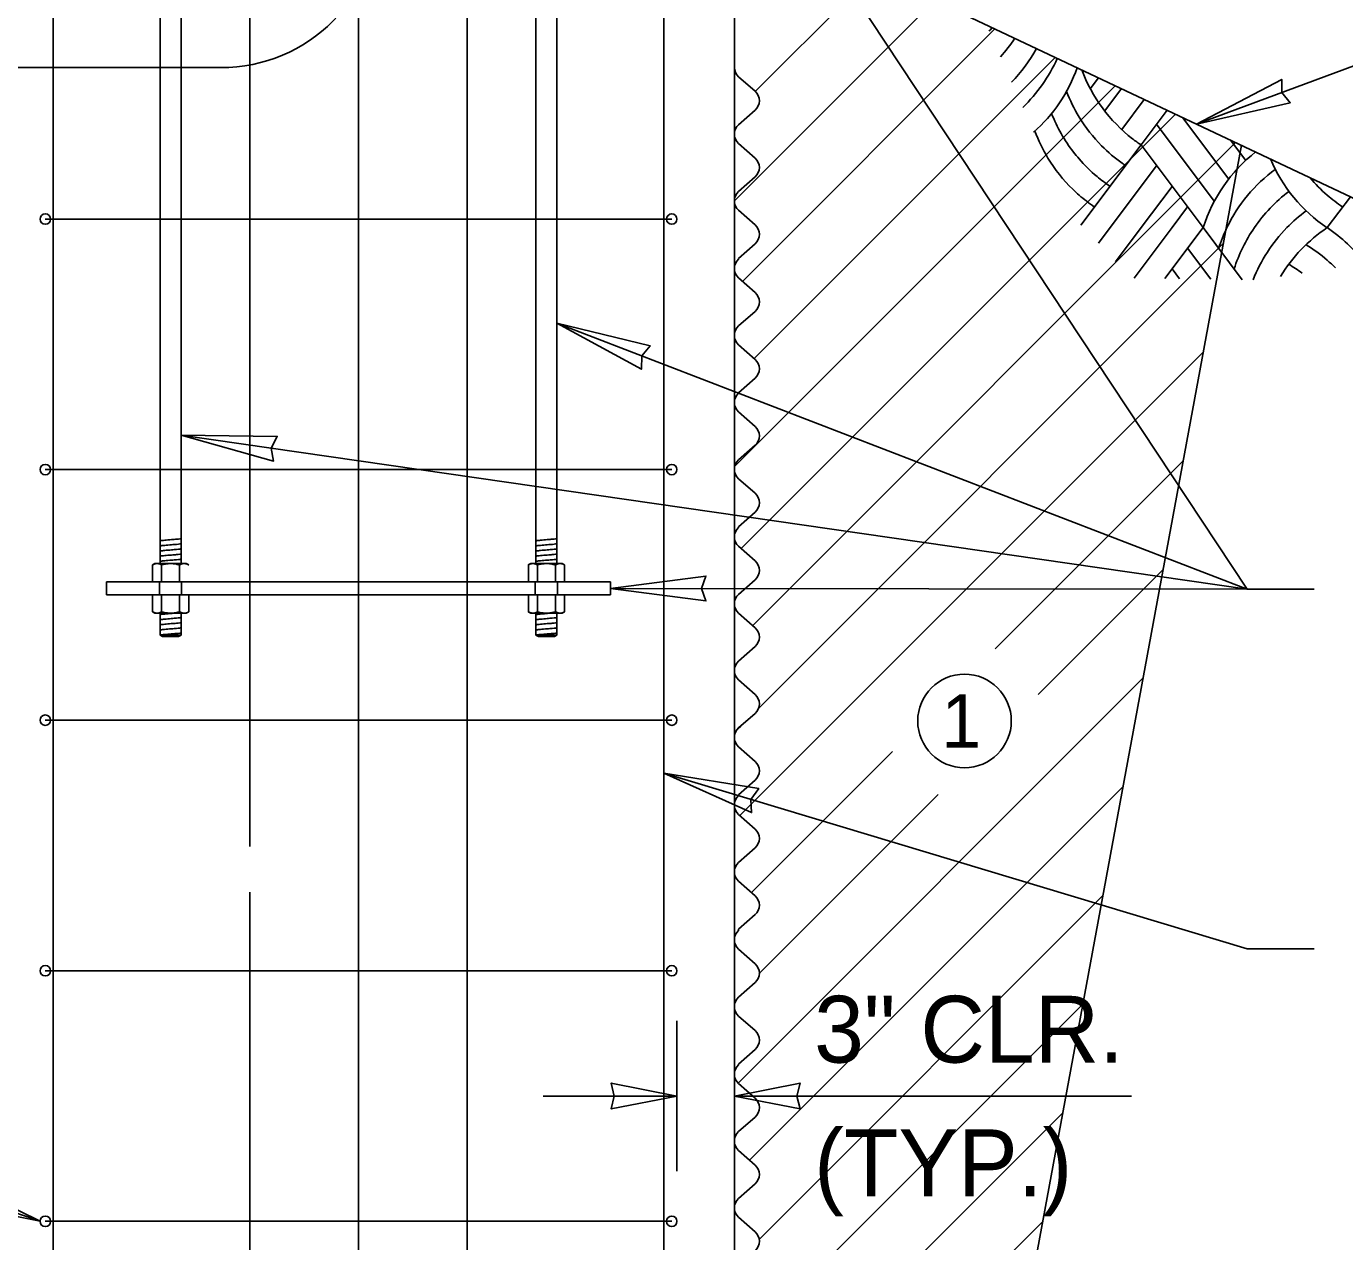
# Model space of a CAD drawing. Extents: x 99862 to 103151, y 100000 to 102076.
# Drawn here: x 101685.3 to 102001, y 101394.1 to 101685.1 of the extents above; entities that cross this region are included whole.
import ezdxf

# ---------------------------------------------------------------- set-up
doc = ezdxf.new("R2010")
doc.units = 0
for name, color, linetype in [('Level 13', 7, 'Continuous'), ('Level 15', 7, 'Continuous'), ('Level 17', 7, 'Continuous'), ('Level 2', 7, 'Continuous'), ('Level 20', 7, 'Continuous'), ('Level 23', 7, 'Continuous'), ('Level 59', 7, 'Continuous'), ('Level 6', 7, 'Continuous'), ('Level 9', 7, 'Continuous')]:
    doc.layers.add(name, color=color, linetype=linetype)

msp = doc.modelspace()

# ---------------------------------------------------------------- linework, layer by layer
at = {"layer": 'Level 13'}
for p, q in [((101691.69, 101338.99), (101691.69, 101798.99)), ((101738.77, 101488.74), (101738.77, 101798.99)), ((101790.85, 101338.99), (101790.85, 101798.99)), ((101837.94, 101338.99), (101837.94, 101798.99)), ((101859.82, 101669.54), (101888.41, 101698.12)), ((101854.82, 101643.32), (101902.81, 101691.32)), ((101856.77, 101624.06), (101917.22, 101684.51)), ((101859.54, 101605.61), (101931.63, 101677.71)), ((101854.95, 101579.82), (101946.04, 101670.91)), ((101856.43, 101560.08), (101960.45, 101664.1)), ((101859.2, 101541.64), (101974.86, 101657.3)), ((101976.23, 101656.65), (101914.81, 101323.99)), ((101839.81, 101638.99), (101689.81, 101638.99)), ((101860.57, 101521.79), (101971.88, 101633.11)), ((101856.14, 101496.15), (101967.08, 101607.09)), ((101839.81, 101578.99), (101689.81, 101578.99)), ((101917.26, 101536.06), (101962.27, 101581.07)), ((101927.56, 101525.15), (101957.47, 101555.06)), ((101855.73, 101432.1), (101952.67, 101529.04)), ((101839.81, 101518.99), (101689.81, 101518.99)), ((101855.74, 101516.96), (101856.36, 101517.58)), ((101858.91, 101477.71), (101892.69, 101511.49)), ((101858.47, 101413.63), (101947.87, 101503.02)), ((101860.66, 101458.25), (101903.6, 101501.18)), ((101738.77, 101338.99), (101738.77, 101477.79)), ((101860.73, 101394.67), (101943.06, 101477.01)), ((101839.81, 101458.99), (101689.81, 101458.99)), ((101855.48, 101368.22), (101938.26, 101450.99)), ((101858.18, 101349.69), (101933.46, 101424.98)), ((101839.81, 101398.99), (101689.81, 101398.99)), ((101860.47, 101330.77), (101928.65, 101398.96))]:
    msp.add_line(p, q, dxfattribs=at)
for centre in [(101689.81, 101638.99), (101839.81, 101638.99), (101689.81, 101578.99), (101839.81, 101578.99), (101689.81, 101518.99), (101839.81, 101518.99), (101689.81, 101458.99), (101839.81, 101458.99), (101689.81, 101398.99), (101839.81, 101398.99)]:
    msp.add_circle(centre, 1.25, dxfattribs=at)
at = {"layer": 'Level 15'}
for p, q in [((101764.81, 101307.99), (101764.81, 102030.59)), ((101977.65, 101550.4), (101825.18, 101780.68)), ((101965.5, 101661.72), (102090.32, 101707.91)), ((101977.65, 101550.4), (101812.31, 101614.02)), ((101977.65, 101550.4), (101722.31, 101587.24)), ((101825.18, 101550.55), (101977.65, 101550.4)), ((101993.65, 101550.4), (101977.65, 101550.4)), ((101837.94, 101506.32), (101977.65, 101464.2)), ((101993.65, 101464.2), (101977.65, 101464.2)), ((101841.06, 101446.99), (101841.06, 101410.99)), ((101688.56, 101398.99), (101560.03, 101442.65)), ((101841.06, 101428.99), (101809.06, 101428.99)), ((101949.93, 101428.99), (101854.81, 101428.99))]:
    msp.add_line(p, q, dxfattribs=at)
for points in [[(101965.5, 101661.72), (101987.95, 101666.84), (101985.92, 101669.27), (101985.88, 101672.44)], [(101812.31, 101614.02), (101832.54, 101603.03), (101832.63, 101606.2), (101834.69, 101608.6)], [(101722.31, 101587.24), (101744.48, 101581.03), (101743.86, 101584.13), (101745.33, 101586.94)], [(101825.18, 101550.55), (101848.01, 101547.54), (101846.96, 101550.53), (101848.02, 101553.51)], [(101837.94, 101506.32), (101858.93, 101496.87), (101858.78, 101500.03), (101860.66, 101502.59)], [(101841.06, 101428.99), (101825.34, 101425.9), (101826.07, 101428.99), (101825.34, 101432.07)], [(101854.81, 101428.99), (101870.54, 101425.9), (101869.81, 101428.99), (101870.54, 101432.07)], [(101688.56, 101398.99), (101665.99, 101403.5), (101667.95, 101405.99), (101667.91, 101409.16)]]:
    msp.add_lwpolyline(points, close=True, dxfattribs=at)
at = {"layer": 'Level 17'}
for p, q in [((101859.8, 101669.58), (101855.83, 101673.08)), ((101855.83, 101661.58), (101859.8, 101665.08)), ((101859.8, 101653.58), (101855.83, 101657.08)), ((101855.83, 101645.58), (101859.8, 101649.08)), ((101859.8, 101637.58), (101855.83, 101641.08)), ((101855.83, 101629.58), (101859.8, 101633.08)), ((101855.83, 101629.38), (101855.83, 101629.58)), ((101859.8, 101621.38), (101855.83, 101624.88)), ((101855.83, 101613.38), (101859.8, 101616.88)), ((101859.8, 101605.38), (101855.83, 101608.88)), ((101855.83, 101597.38), (101859.8, 101600.88)), ((101855.83, 101597.31), (101855.83, 101597.38)), ((101859.8, 101589.31), (101855.83, 101592.81)), ((101855.83, 101581.31), (101859.8, 101584.81)), ((101859.8, 101573.31), (101855.83, 101576.81)), ((101855.83, 101565.31), (101859.8, 101568.81)), ((101855.83, 101565.12), (101855.83, 101565.31)), ((101859.8, 101557.12), (101855.83, 101560.62)), ((101855.83, 101549.12), (101859.8, 101552.62)), ((101859.8, 101541.12), (101855.83, 101544.62)), ((101855.83, 101533.12), (101859.8, 101536.62)), ((101859.8, 101525.12), (101855.83, 101528.62)), ((101855.83, 101517.12), (101859.8, 101520.62)), ((101859.8, 101509.12), (101855.83, 101512.62)), ((101855.83, 101501.12), (101859.8, 101504.62)), ((101855.83, 101500.92), (101855.83, 101501.12)), ((101859.8, 101492.92), (101855.83, 101496.42)), ((101855.83, 101484.92), (101859.8, 101488.42)), ((101859.8, 101476.92), (101855.83, 101480.42)), ((101855.83, 101468.92), (101859.8, 101472.42)), ((101855.83, 101468.65), (101855.83, 101468.92)), ((101859.8, 101460.65), (101855.83, 101464.15)), ((101855.83, 101452.65), (101859.8, 101456.15)), ((101859.8, 101444.65), (101855.83, 101448.15)), ((101855.83, 101436.65), (101859.8, 101440.15)), ((101855.83, 101436.46), (101855.83, 101436.65)), ((101859.8, 101428.46), (101855.83, 101431.96)), ((101855.83, 101420.46), (101859.8, 101423.96)), ((101859.8, 101412.46), (101855.83, 101415.96)), ((101855.83, 101404.46), (101859.8, 101407.96)), ((101859.8, 101396.46), (101855.83, 101399.96))]:
    msp.add_line(p, q, dxfattribs=at)
for centre, start, end in [((101857.81, 101675.33), 181.5884, 228.5904), ((101857.81, 101667.33), 311.4096, 48.5904), ((101857.81, 101659.33), 131.4096, 228.5904), ((101857.81, 101651.33), 311.4096, 48.5904), ((101857.81, 101643.33), 131.4096, 228.5904), ((101857.81, 101635.33), 311.4096, 48.5904), ((101857.81, 101627.13), 131.4096, 228.5904), ((101857.81, 101619.13), 311.4096, 48.5904), ((101857.81, 101611.13), 131.4096, 228.5904), ((101857.81, 101603.13), 311.4096, 48.5904), ((101857.81, 101595.06), 131.4096, 228.5904), ((101857.81, 101587.06), 311.4096, 48.5904), ((101857.81, 101579.06), 131.4096, 228.5904), ((101857.81, 101571.06), 311.4096, 48.5904), ((101857.81, 101562.87), 131.4096, 228.5904), ((101857.81, 101554.87), 311.4096, 48.5904), ((101857.81, 101546.87), 131.4096, 228.5904), ((101857.81, 101538.87), 311.4096, 48.5904), ((101857.81, 101530.87), 131.4096, 228.5904), ((101857.81, 101522.87), 311.4096, 48.5904), ((101857.81, 101514.87), 131.4096, 228.5904), ((101857.81, 101506.87), 311.4096, 48.5904), ((101857.81, 101498.67), 131.4096, 228.5904), ((101857.81, 101490.67), 311.4096, 48.5904), ((101857.81, 101482.67), 131.4096, 228.5904), ((101857.81, 101474.67), 311.4096, 48.5904), ((101857.81, 101466.4), 131.4096, 228.5904), ((101857.81, 101458.4), 311.4096, 48.5904), ((101857.81, 101450.4), 131.4096, 228.5904), ((101857.81, 101442.4), 311.4096, 48.5904), ((101857.81, 101434.21), 131.4096, 228.5904), ((101857.81, 101426.21), 311.4096, 48.5904), ((101857.81, 101418.21), 131.4096, 228.5904), ((101857.81, 101410.21), 311.4096, 48.5904), ((101857.81, 101402.21), 131.4096, 228.5904), ((101857.81, 101394.21), 311.4096, 48.5904)]:
    msp.add_arc(centre, 3, start, end, dxfattribs=at)
at = {"layer": 'Level 2'}
msp.add_line((101854.81, 101323.99), (101854.81, 101803.99), dxfattribs=at)
at = {"layer": 'Level 20'}
msp.add_circle((101909.93, 101518.81), 11.2, dxfattribs=at)
at = {"layer": 'Level 23'}
for p, q in [((101717.31, 101776.3), (101717.31, 101556.49)), ((101722.31, 101776.3), (101722.31, 101556.49)), ((101807.31, 101776.3), (101807.31, 101556.49)), ((101812.31, 101776.3), (101812.31, 101556.49)), ((101825.18, 101552.11), (101704.43, 101552.11)), ((101704.43, 101552.11), (101704.43, 101548.99)), ((101717.15, 101552.11), (101717.15, 101548.99)), ((101722.46, 101552.11), (101722.46, 101548.99)), ((101807.15, 101552.11), (101807.15, 101548.99)), ((101812.46, 101552.11), (101812.46, 101548.99)), ((101825.18, 101548.99), (101825.18, 101552.11)), ((101704.43, 101548.99), (101825.18, 101548.99)), ((101717.31, 101544.61), (101717.31, 101539.33)), ((101722.31, 101544.61), (101722.31, 101539.33)), ((101807.31, 101544.61), (101807.31, 101539.33)), ((101812.31, 101544.61), (101812.31, 101539.33)), ((101717.91, 101538.99), (101717.31, 101539.33)), ((101722.31, 101539.33), (101717.31, 101539.33)), ((101717.91, 101538.99), (101721.71, 101538.99)), ((101721.71, 101538.99), (101722.31, 101539.33)), ((101812.31, 101539.33), (101807.31, 101539.33)), ((101807.91, 101538.99), (101807.31, 101539.33)), ((101807.91, 101538.99), (101811.71, 101538.99)), ((101811.71, 101538.99), (101812.31, 101539.33))]:
    msp.add_line(p, q, dxfattribs=at)
for points in [[(101717.33, 101561.92), (101717.34, 101561.93), (101717.34, 101561.93), (101717.48, 101562), (101718.22, 101562.06), (101720.13, 101562.24), (101721.28, 101562.32), (101722.12, 101562.42), (101722.27, 101562.45), (101722.31, 101562.49)], [(101717.33, 101560.69), (101717.34, 101560.7), (101717.34, 101560.7), (101717.48, 101560.77), (101718.22, 101560.83), (101720.13, 101561.02), (101721.28, 101561.09), (101722.12, 101561.19), (101722.27, 101561.22), (101722.31, 101561.26)], [(101717.33, 101559.47), (101717.34, 101559.47), (101717.34, 101559.47), (101717.48, 101559.54), (101718.22, 101559.61), (101720.14, 101559.79), (101721.28, 101559.86), (101722.12, 101559.96), (101722.27, 101560), (101722.31, 101560.03)], [(101807.33, 101561.92), (101807.34, 101561.93), (101807.34, 101561.93), (101807.48, 101562), (101808.22, 101562.06), (101810.13, 101562.24), (101811.28, 101562.32), (101812.12, 101562.42), (101812.27, 101562.45), (101812.31, 101562.49)], [(101807.33, 101560.69), (101807.34, 101560.7), (101807.34, 101560.7), (101807.48, 101560.77), (101808.22, 101560.83), (101810.13, 101561.02), (101811.28, 101561.09), (101812.12, 101561.19), (101812.27, 101561.22), (101812.31, 101561.26)], [(101807.33, 101559.47), (101807.34, 101559.47), (101807.34, 101559.47), (101807.48, 101559.54), (101808.22, 101559.61), (101810.14, 101559.79), (101811.28, 101559.86), (101812.12, 101559.96), (101812.27, 101560), (101812.31, 101560.03)], [(101717.32, 101558.24), (101717.32, 101558.24), (101717.32, 101558.24), (101717.47, 101558.31), (101718.2, 101558.38), (101720.12, 101558.56), (101721.26, 101558.63), (101722.1, 101558.73), (101722.26, 101558.77), (101722.29, 101558.8)], [(101717.33, 101557.01), (101717.34, 101557.01), (101717.34, 101557.01), (101717.48, 101557.08), (101718.22, 101557.15), (101720.13, 101557.33), (101721.28, 101557.4), (101722.12, 101557.51), (101722.27, 101557.54), (101722.31, 101557.57)], [(101807.32, 101558.24), (101807.32, 101558.24), (101807.32, 101558.24), (101807.47, 101558.31), (101808.2, 101558.38), (101810.12, 101558.56), (101811.26, 101558.63), (101812.1, 101558.73), (101812.26, 101558.77), (101812.29, 101558.8)], [(101807.33, 101557.01), (101807.34, 101557.01), (101807.34, 101557.01), (101807.48, 101557.08), (101808.22, 101557.15), (101810.13, 101557.33), (101811.28, 101557.4), (101812.12, 101557.51), (101812.27, 101557.54), (101812.31, 101557.57)], [(101717.31, 101544.25), (101717.31, 101544.25), (101717.32, 101544.26), (101717.46, 101544.33), (101718.2, 101544.39), (101719.64, 101544.53), (101720.23, 101544.57), (101720.7, 101544.61)], [(101807.31, 101544.25), (101807.31, 101544.25), (101807.32, 101544.26), (101807.46, 101544.33), (101808.2, 101544.39), (101809.64, 101544.53), (101810.23, 101544.57), (101810.7, 101544.61)], [(101717.29, 101540.56), (101717.3, 101540.57), (101717.3, 101540.57), (101717.44, 101540.64), (101718.18, 101540.7), (101720.09, 101540.89), (101721.24, 101540.96), (101722.08, 101541.06), (101722.23, 101541.09), (101722.27, 101541.13)], [(101717.31, 101543.02), (101717.31, 101543.02), (101717.32, 101543.03), (101717.46, 101543.1), (101718.2, 101543.16), (101720.11, 101543.34), (101721.25, 101543.42), (101722.09, 101543.52), (101722.25, 101543.55), (101722.29, 101543.59)], [(101717.31, 101541.79), (101717.31, 101541.8), (101717.32, 101541.8), (101717.46, 101541.87), (101718.2, 101541.93), (101720.11, 101542.12), (101721.25, 101542.19), (101722.09, 101542.29), (101722.25, 101542.32), (101722.29, 101542.36)], [(101807.29, 101540.56), (101807.3, 101540.57), (101807.3, 101540.57), (101807.44, 101540.64), (101808.18, 101540.7), (101810.09, 101540.89), (101811.24, 101540.96), (101812.08, 101541.06), (101812.23, 101541.09), (101812.27, 101541.13)], [(101807.31, 101543.02), (101807.31, 101543.02), (101807.32, 101543.03), (101807.46, 101543.1), (101808.2, 101543.16), (101810.11, 101543.34), (101811.25, 101543.42), (101812.09, 101543.52), (101812.25, 101543.55), (101812.29, 101543.59)], [(101807.31, 101541.79), (101807.31, 101541.8), (101807.32, 101541.8), (101807.46, 101541.87), (101808.2, 101541.93), (101810.11, 101542.12), (101811.25, 101542.19), (101812.09, 101542.29), (101812.25, 101542.32), (101812.29, 101542.36)], [(101717.31, 101539.33), (101717.31, 101539.34), (101717.32, 101539.34), (101717.46, 101539.41), (101718.2, 101539.48), (101720.11, 101539.66), (101721.25, 101539.73), (101722.09, 101539.83), (101722.25, 101539.87), (101722.28, 101539.9)], [(101807.31, 101539.33), (101807.31, 101539.34), (101807.32, 101539.34), (101807.46, 101539.41), (101808.2, 101539.48), (101810.11, 101539.66), (101811.25, 101539.73), (101812.09, 101539.83), (101812.25, 101539.87), (101812.28, 101539.9)]]:
    msp.add_open_spline(points, degree=3, dxfattribs=at)
at = {"layer": 'Level 59'}
for p, q in [((101916.16, 101685.02), (101916.41, 101684.68)), ((101940.05, 101670.19), (101942.02, 101672.81)), ((101943.5, 101664.88), (101947.5, 101670.22)), ((101947.57, 101660.42), (101952.98, 101667.63)), ((101952.23, 101656.72), (101958.46, 101665.04)), ((101955.94, 101661.67), (101969.75, 101643.26)), ((101962.14, 101663.3), (101973.19, 101648.57)), ((101973.64, 101657.87), (101977.27, 101653.03)), ((101937.82, 101637.52), (101952.23, 101656.72)), ((101952.23, 101656.72), (101967.08, 101636.93)), ((101944.8, 101636.93), (101955.94, 101651.77)), ((101952.23, 101636.93), (101959.65, 101646.82)), ((101959.65, 101636.93), (101963.36, 101641.88)), ((101996.77, 101636.93), (102002.33, 101644.33)), ((101942.03, 101633.23), (101944.8, 101636.93)), ((101946.11, 101628.77), (101952.23, 101636.93)), ((101950.59, 101624.84), (101959.65, 101636.93)), ((101957.93, 101624.73), (101967.08, 101636.93)), ((101967.08, 101636.93), (101976.42, 101624.47)), ((101963.36, 101631.98), (101968.91, 101624.57)), ((101959.65, 101627.03), (101961.41, 101624.68))]:
    msp.add_line(p, q, dxfattribs=at)
msp.add_lwpolyline([(102082.04, 101606.68), (101854.81, 101713.99)], dxfattribs=at)
for centre, start, end in [((101886.72, 101707.71), 320.8198, 322.5062), ((101890.43, 101702.76), 318.4263, 326.9825), ((101894.14, 101697.81), 316.0781, 331.4116), ((101897.86, 101692.86), 313.7689, 335.821), ((101901.57, 101687.91), 311.4933, 340.2369), ((101973.19, 101687.91), 200.5897, 232.2158), ((101969.48, 101682.96), 200.8778, 211.332), ((101965.76, 101678.01), 201.4344, 217.7744), ((101969.48, 101682.96), 211.3319, 224.7103), ((101962.05, 101673.06), 200.2432, 211.2107), ((101973.19, 101687.91), 232.2158, 236.0964), ((101965.76, 101678.01), 217.7744, 220.9416), ((101969.48, 101682.96), 224.7103, 234.573), ((102002.89, 101625.54), 128.2474, 162.3566), ((101962.05, 101673.06), 211.2107, 225.8168), ((101965.76, 101678.01), 220.9415, 230.1262), ((101969.48, 101682.96), 234.573, 236.0964), ((102017.74, 101668.11), 203.0973, 236.0964), ((101965.76, 101678.01), 230.1262, 236.0964), ((102006.6, 101620.59), 126.3063, 154.2266), ((102021.45, 101673.06), 220.0625, 228.9599), ((101962.05, 101673.06), 225.8168, 228.9599), ((102010.31, 101615.64), 127.1006, 145.4911), ((101962.05, 101673.06), 228.9599, 236.0964), ((102021.45, 101673.06), 228.9599, 236.0964), ((102014.02, 101610.69), 126.331, 135.7128), ((102006.6, 101620.59), 154.2265, 162.3566), ((102010.31, 101615.64), 145.491, 162.3566), ((102014.02, 101610.69), 135.7127, 158.5506), ((102017.74, 101605.74), 123.9036, 148.7505), ((101975.81, 101605.74), 37.035, 56.0963), ((101972.1, 101600.79), 48.9597, 58.5465), ((101968.39, 101595.84), 53.466, 59.3021), ((101972.1, 101600.79), 44.8178, 48.9597)]:
    msp.add_arc(centre, 37.58, start, end, dxfattribs=at)
at = {"layer": 'Level 6'}
msp.add_line((101731.81, 101675.24), (101674.81, 101675.24), dxfattribs=at)
msp.add_arc((101731.81, 101713.24), 38, 270, 0, dxfattribs=at)
at = {"layer": 'Level 9'}
for p, q in [((101716.06, 101556.49), (101715.47, 101556.15)), ((101715.48, 101556.15), (101715.48, 101552.11)), ((101723, 101556.49), (101716.06, 101556.49)), ((101716.59, 101556.49), (101716.54, 101556.49)), ((101717.64, 101556.15), (101717.64, 101552.11)), ((101719.9, 101556.49), (101719.72, 101556.49)), ((101721.97, 101556.15), (101721.97, 101552.11)), ((101723.11, 101556.49), (101723, 101556.49)), ((101723.02, 101556.49), (101723.09, 101556.49)), ((101723.56, 101556.49), (101723.09, 101556.49)), ((101723.56, 101556.49), (101724.14, 101556.15)), ((101806.06, 101556.49), (101805.47, 101556.15)), ((101805.48, 101556.15), (101805.48, 101552.11)), ((101813, 101556.49), (101806.06, 101556.49)), ((101806.59, 101556.49), (101806.54, 101556.49)), ((101807.64, 101556.15), (101807.64, 101552.11)), ((101809.9, 101556.49), (101809.72, 101556.49)), ((101811.97, 101556.15), (101811.97, 101552.11)), ((101813.11, 101556.49), (101813, 101556.49)), ((101813.02, 101556.49), (101813.09, 101556.49)), ((101813.56, 101556.49), (101813.09, 101556.49)), ((101813.56, 101556.49), (101814.14, 101556.15)), ((101814.14, 101556.15), (101814.14, 101552.11)), ((101715.48, 101544.95), (101715.48, 101548.99)), ((101717.64, 101544.95), (101717.64, 101548.99)), ((101721.97, 101544.95), (101721.97, 101548.99)), ((101724.14, 101544.95), (101724.14, 101548.99)), ((101805.48, 101544.95), (101805.48, 101548.99)), ((101807.64, 101544.95), (101807.64, 101548.99)), ((101811.97, 101544.95), (101811.97, 101548.99)), ((101814.14, 101544.95), (101814.14, 101548.99)), ((101716.06, 101544.61), (101715.47, 101544.95)), ((101723, 101544.61), (101716.06, 101544.61)), ((101716.59, 101544.61), (101716.54, 101544.61)), ((101719.9, 101544.61), (101719.72, 101544.61)), ((101723.11, 101544.61), (101723, 101544.61)), ((101723.02, 101544.61), (101723.09, 101544.61)), ((101723.56, 101544.61), (101723.09, 101544.61)), ((101723.56, 101544.61), (101724.14, 101544.95)), ((101806.06, 101544.61), (101805.47, 101544.95)), ((101813, 101544.61), (101806.06, 101544.61)), ((101806.59, 101544.61), (101806.54, 101544.61)), ((101809.9, 101544.61), (101809.72, 101544.61)), ((101813.11, 101544.61), (101813, 101544.61)), ((101813.02, 101544.61), (101813.09, 101544.61)), ((101813.56, 101544.61), (101813.09, 101544.61)), ((101813.56, 101544.61), (101814.14, 101544.95))]:
    msp.add_line(p, q, dxfattribs=at)
for points, degree in [([(101716.54, 101556.49), (101716.52, 101556.49), (101716.5, 101556.49), (101716.49, 101556.48), (101716.15, 101556.47), (101715.8, 101556.34), (101715.48, 101556.15)], 3), ([(101717.64, 101556.15), (101717.3, 101556.35), (101716.94, 101556.48), (101716.59, 101556.49)], 2), ([(101719.72, 101556.49), (101719.56, 101556.48), (101719.41, 101556.48), (101719.25, 101556.46), (101718.71, 101556.42), (101718.17, 101556.3), (101717.64, 101556.15)], 3), ([(101721.97, 101556.15), (101721.81, 101556.2), (101721.64, 101556.24), (101721.47, 101556.28), (101720.95, 101556.4), (101720.43, 101556.48), (101719.9, 101556.49)], 3), ([(101723, 101556.49), (101723, 101556.49), (101722.99, 101556.49), (101722.98, 101556.49), (101722.64, 101556.47), (101722.3, 101556.34), (101721.97, 101556.15)], 3), ([(101724.14, 101556.15), (101723.8, 101556.35), (101723.45, 101556.48), (101723.11, 101556.49)], 2), ([(101806.54, 101556.49), (101806.52, 101556.49), (101806.5, 101556.49), (101806.49, 101556.48), (101806.15, 101556.47), (101805.8, 101556.34), (101805.48, 101556.15)], 3), ([(101807.64, 101556.15), (101807.3, 101556.35), (101806.94, 101556.48), (101806.59, 101556.49)], 2), ([(101809.72, 101556.49), (101809.56, 101556.48), (101809.41, 101556.48), (101809.25, 101556.46), (101808.71, 101556.42), (101808.17, 101556.3), (101807.64, 101556.15)], 3), ([(101811.97, 101556.15), (101811.81, 101556.2), (101811.64, 101556.24), (101811.47, 101556.28), (101810.95, 101556.4), (101810.43, 101556.48), (101809.9, 101556.49)], 3), ([(101813, 101556.49), (101813, 101556.49), (101812.99, 101556.49), (101812.98, 101556.49), (101812.64, 101556.47), (101812.3, 101556.34), (101811.97, 101556.15)], 3), ([(101814.14, 101556.15), (101813.8, 101556.35), (101813.45, 101556.48), (101813.11, 101556.49)], 2), ([(101716.54, 101544.61), (101716.52, 101544.61), (101716.5, 101544.61), (101716.49, 101544.61), (101716.15, 101544.63), (101715.8, 101544.76), (101715.48, 101544.95)], 3), ([(101717.64, 101544.95), (101717.3, 101544.75), (101716.94, 101544.62), (101716.59, 101544.61)], 2), ([(101717.64, 101544.95), (101718.17, 101544.79), (101718.71, 101544.68), (101719.25, 101544.63), (101719.44, 101544.62), (101719.62, 101544.61), (101719.81, 101544.61)], 3), ([(101721.97, 101544.95), (101721.81, 101544.9), (101721.64, 101544.85), (101721.47, 101544.81), (101720.95, 101544.69), (101720.43, 101544.62), (101719.9, 101544.61)], 3), ([(101723, 101544.61), (101723, 101544.61), (101722.99, 101544.61), (101722.98, 101544.61), (101722.64, 101544.63), (101722.3, 101544.76), (101721.97, 101544.95)], 3), ([(101724.14, 101544.95), (101723.8, 101544.75), (101723.45, 101544.62), (101723.11, 101544.61)], 2), ([(101806.54, 101544.61), (101806.52, 101544.61), (101806.5, 101544.61), (101806.49, 101544.61), (101806.15, 101544.63), (101805.8, 101544.76), (101805.48, 101544.95)], 3), ([(101807.64, 101544.95), (101807.3, 101544.75), (101806.94, 101544.62), (101806.59, 101544.61)], 2), ([(101807.64, 101544.95), (101808.17, 101544.79), (101808.71, 101544.68), (101809.25, 101544.63), (101809.44, 101544.62), (101809.62, 101544.61), (101809.81, 101544.61)], 3), ([(101811.97, 101544.95), (101811.81, 101544.9), (101811.64, 101544.85), (101811.47, 101544.81), (101810.95, 101544.69), (101810.43, 101544.62), (101809.9, 101544.61)], 3), ([(101813, 101544.61), (101813, 101544.61), (101812.99, 101544.61), (101812.98, 101544.61), (101812.64, 101544.63), (101812.3, 101544.76), (101811.97, 101544.95)], 3), ([(101814.14, 101544.95), (101813.8, 101544.75), (101813.45, 101544.62), (101813.11, 101544.61)], 2)]:
    msp.add_open_spline(points, degree=degree, dxfattribs=at)

# ---------------------------------------------------------------- texts
at = {"layer": 'Level 20'}
for s, height, p in [('1', 12.8, (101904.37, 101512.41)), ('3" CLR.', 16, (101873.93, 101436.99)), ('(TYP.)', 16, (101873.93, 101404.99))]:
    msp.add_text(s, height=height, dxfattribs=at).set_placement(p)

doc.saveas('drawing.dxf')
